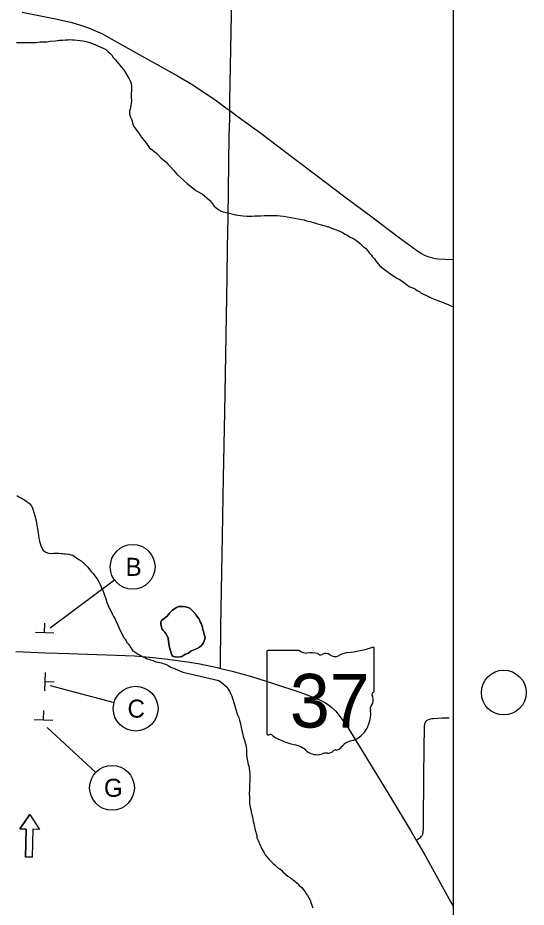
# Model space of a CAD drawing. Extents: x 1633.3 to 1707.6, y 1081.5 to 1106.
# Drawn here: x 1644.25 to 1648.64, y 1094.16 to 1101.85 of the extents above; entities that cross this region are included whole.
import ezdxf

# ---------------------------------------------------------------- set-up
doc = ezdxf.new("R2010")
doc.units = 0
for name, color, linetype in [('GM_X_Minor_Lake', 7, 'Continuous'), ('GM_X_Minor_River', 7, 'Continuous'), ('GM_X_State_Route', 7, 'Continuous'), ('GM_X_State_Shield', 7, 'Continuous'), ('GM_X_Township_Road', 7, 'Continuous'), ('SH_Data', 7, 'Continuous'), ('SH_Text', 7, 'Continuous'), ('SN_P_Signs', 7, 'Continuous')]:
    doc.layers.add(name, color=color, linetype=linetype)

msp = doc.modelspace()

# ---------------------------------------------------------------- linework, layer by layer
at = {"layer": 'GM_X_Minor_Lake'}
for points in [[(1645.4903, 1096.6358), (1645.5391, 1096.6727), (1645.5582, 1096.6965), (1645.5827, 1096.723), (1645.6044, 1096.7388), (1645.6206, 1096.7493), (1645.6395, 1096.7571), (1645.6583, 1096.7568), (1645.6771, 1096.7566), (1645.6986, 1096.7536), (1645.72, 1096.748), (1645.7387, 1096.7397), (1645.7599, 1096.7207), (1645.7732, 1096.7071), (1645.7837, 1096.6936), (1645.7943, 1096.6774), (1645.8128, 1096.653), (1645.8207, 1096.6395), (1645.8259, 1096.6261), (1645.8337, 1096.6099), (1645.8389, 1096.5964), (1645.8518, 1096.5507), (1645.8569, 1096.5292), (1645.862, 1096.5077), (1645.8671, 1096.4889), (1645.8642, 1096.4755), (1645.8587, 1096.4596), (1645.8531, 1096.4462), (1645.8449, 1096.4329), (1645.834, 1096.417), (1645.8204, 1096.4065), (1645.7988, 1096.3934), (1645.7691, 1096.3831), (1645.7448, 1096.37), (1645.7231, 1096.3542), (1645.6988, 1096.3438), (1645.6852, 1096.3359), (1645.6663, 1096.3255), (1645.6529, 1096.323), (1645.6259, 1096.318), (1645.6099, 1096.3208), (1645.5911, 1096.3238), (1645.5806, 1096.34), (1645.5754, 1096.3534), (1645.5702, 1096.3669), (1645.5624, 1096.3911), (1645.5599, 1096.4045), (1645.5574, 1096.418), (1645.5549, 1096.4367), (1645.5525, 1096.4582), (1645.5474, 1096.4824), (1645.5397, 1096.5039), (1645.5292, 1096.5228), (1645.5186, 1096.5363), (1645.5027, 1096.5526), (1645.4948, 1096.5661), (1645.4923, 1096.5795), (1645.4846, 1096.6064), (1645.4847, 1096.6198), (1645.4903, 1096.6358)], [(1645.834, 1096.417), (1645.8449, 1096.4329), (1645.8531, 1096.4462), (1645.8587, 1096.4596), (1645.8642, 1096.4755), (1645.8671, 1096.4889), (1645.862, 1096.5077), (1645.8569, 1096.5292), (1645.8518, 1096.5507), (1645.8389, 1096.5964), (1645.8337, 1096.6099), (1645.8259, 1096.6261), (1645.8207, 1096.6395), (1645.8128, 1096.653), (1645.7943, 1096.6774), (1645.7837, 1096.6936), (1645.7732, 1096.7071), (1645.7599, 1096.7207), (1645.7387, 1096.7397), (1645.72, 1096.748), (1645.6986, 1096.7536), (1645.6771, 1096.7566), (1645.6583, 1096.7568), (1645.6395, 1096.7571), (1645.6206, 1096.7493), (1645.6044, 1096.7388), (1645.5827, 1096.723), (1645.5582, 1096.6965), (1645.5391, 1096.6727), (1645.4903, 1096.6358)], [(1645.4903, 1096.6358), (1645.4847, 1096.6198), (1645.4846, 1096.6064), (1645.4923, 1096.5795), (1645.4948, 1096.5661), (1645.5027, 1096.5526), (1645.5186, 1096.5363), (1645.5292, 1096.5228), (1645.5397, 1096.5039), (1645.5474, 1096.4824), (1645.5525, 1096.4582), (1645.5549, 1096.4367), (1645.5574, 1096.418), (1645.5599, 1096.4045), (1645.5624, 1096.3911), (1645.5702, 1096.3669), (1645.5754, 1096.3534), (1645.5806, 1096.34), (1645.5911, 1096.3238), (1645.6099, 1096.3208), (1645.6259, 1096.318), (1645.6529, 1096.323), (1645.6663, 1096.3255), (1645.6852, 1096.3359), (1645.6988, 1096.3438), (1645.7231, 1096.3542), (1645.7448, 1096.37), (1645.7691, 1096.3831), (1645.7988, 1096.3934), (1645.8204, 1096.4065), (1645.834, 1096.417)]]:
    msp.add_lwpolyline(points, dxfattribs=at)
at = {"layer": 'GM_X_Minor_River'}
for points in [[(1644.2374, 1101.6373), (1644.2696, 1101.6368), (1644.2964, 1101.6365), (1644.326, 1101.6388), (1644.3556, 1101.6384), (1644.3824, 1101.638), (1644.4039, 1101.6378), (1644.4227, 1101.6402), (1644.4416, 1101.6426), (1644.4711, 1101.6422), (1644.5007, 1101.6445), (1644.5276, 1101.6495), (1644.5733, 1101.6516), (1644.6082, 1101.6565), (1644.6378, 1101.6588), (1644.662, 1101.6612), (1644.6835, 1101.6609), (1644.6996, 1101.6633), (1644.7157, 1101.6605), (1644.7345, 1101.6602), (1644.7613, 1101.6572), (1644.8149, 1101.6511), (1644.839, 1101.6454), (1644.8685, 1101.637), (1644.8925, 1101.6287), (1644.9086, 1101.6231), (1644.9273, 1101.6148), (1644.946, 1101.6065), (1644.9674, 1101.5982), (1644.986, 1101.5873), (1645.0101, 1101.5762), (1645.026, 1101.56), (1645.0446, 1101.5463), (1645.0605, 1101.5274), (1645.0737, 1101.5084), (1645.0922, 1101.4868), (1645.1054, 1101.4732), (1645.1187, 1101.4569), (1645.1292, 1101.4434), (1645.1425, 1101.4272), (1645.161, 1101.4055), (1645.1768, 1101.3812), (1645.1978, 1101.3461), (1645.211, 1101.3245), (1645.2188, 1101.3056), (1645.2267, 1101.2921), (1645.2292, 1101.276), (1645.2317, 1101.2599), (1645.2315, 1101.2439), (1645.2312, 1101.2224), (1645.2281, 1101.193), (1645.2277, 1101.1609), (1645.2301, 1101.1367), (1645.2298, 1101.1099), (1645.2268, 1101.0912), (1645.2211, 1101.0618), (1645.2155, 1101.0432), (1645.2152, 1101.0191), (1645.2229, 1100.9922), (1645.2307, 1100.9733), (1645.2359, 1100.9572), (1645.241, 1100.9384), (1645.2462, 1100.9222), (1645.2567, 1100.9033), (1645.2937, 1100.852), (1645.3095, 1100.8303), (1645.328, 1100.806), (1645.3518, 1100.7762), (1645.386, 1100.7249), (1645.4473, 1100.6812), (1645.4844, 1100.6405), (1645.5136, 1100.616), (1645.5322, 1100.6024), (1645.5481, 1100.5834), (1645.572, 1100.559), (1645.5958, 1100.5319), (1645.6222, 1100.4994), (1645.6514, 1100.4722), (1645.6806, 1100.4451), (1645.7125, 1100.4179), (1645.7524, 1100.3852), (1645.7869, 1100.358), (1645.8243, 1100.336), (1645.8456, 1100.3251), (1645.8616, 1100.3115), (1645.8828, 1100.2924), (1645.9067, 1100.2734), (1645.9252, 1100.249), (1645.9464, 1100.2219), (1645.9756, 1100.1975), (1646.0023, 1100.181), (1646.0236, 1100.1727), (1646.0504, 1100.167), (1646.0665, 1100.1641)], [(1646.0665, 1100.1641), (1646.0879, 1100.1585), (1646.1093, 1100.1528), (1646.1307, 1100.1472), (1646.1495, 1100.1443), (1646.1736, 1100.1413), (1646.1978, 1100.1383), (1646.23, 1100.1352), (1646.2568, 1100.1348), (1646.2756, 1100.1346), (1646.2971, 1100.137), (1646.324, 1100.1393), (1646.3508, 1100.1389), (1646.3777, 1100.1413), (1646.4126, 1100.1408), (1646.4476, 1100.1404), (1646.469, 1100.1401), (1646.4905, 1100.1398), (1646.5173, 1100.1368), (1646.5468, 1100.1337), (1646.5763, 1100.1306), (1646.7049, 1100.1048), (1646.7237, 1100.1019), (1646.7451, 1100.0936), (1646.7745, 1100.0879), (1646.804, 1100.0794), (1646.8307, 1100.071), (1646.8709, 1100.0598), (1646.9137, 1100.0485), (1646.9431, 1100.0401), (1646.9618, 1100.0318), (1646.9859, 1100.0235), (1647.0019, 1100.0179), (1647.0153, 1100.0124), (1647.0313, 1100.0041), (1647.0553, 1099.9931), (1647.0793, 1099.9794), (1647.1007, 1099.9684), (1647.122, 1099.9547), (1647.1513, 1099.9409), (1647.178, 1099.9245), (1647.2072, 1099.8973), (1647.2364, 1099.8702), (1647.2551, 1099.8592), (1647.2735, 1099.8349), (1647.2868, 1099.8186), (1647.3026, 1099.7997), (1647.3159, 1099.7834), (1647.3317, 1099.7645), (1647.3476, 1099.7428), (1647.3635, 1099.7239), (1647.3767, 1099.7076), (1647.3926, 1099.694), (1647.4192, 1099.6749), (1647.4512, 1099.6504), (1647.4911, 1099.6204), (1647.531, 1099.5958), (1647.5524, 1099.5875), (1647.5657, 1099.5766), (1647.579, 1099.5657), (1647.5976, 1099.552), (1647.6189, 1099.5357), (1647.6376, 1099.5247), (1647.6509, 1099.5165), (1647.6696, 1099.5109), (1647.6856, 1099.5027), (1647.7016, 1099.4917), (1647.7203, 1099.4835), (1647.7362, 1099.4699), (1647.7816, 1099.4478), (1647.8003, 1099.4395), (1647.8216, 1099.4286), (1647.8484, 1099.4175), (1647.8805, 1099.4064), (1647.9018, 1099.398), (1647.9259, 1099.387), (1647.9446, 1099.3787), (1647.9686, 1099.3704), (1647.9927, 1099.3593), (1648.0121, 1099.3526)], [(1644.2417, 1097.7183), (1644.2577, 1097.7074), (1644.2737, 1097.6991), (1644.2897, 1097.6882), (1644.3057, 1097.68), (1644.3217, 1097.669), (1644.3376, 1097.6581), (1644.3536, 1097.6472), (1644.3642, 1097.631), (1644.3747, 1097.6121), (1644.3824, 1097.5906), (1644.3901, 1097.561), (1644.3979, 1097.5341), (1644.4056, 1097.5072), (1644.4106, 1097.4804), (1644.413, 1097.4589), (1644.418, 1097.4321), (1644.4232, 1097.4105), (1644.4256, 1097.3918), (1644.4281, 1097.3757), (1644.4304, 1097.3462)], [(1644.4304, 1097.3462), (1644.4355, 1097.322), (1644.4433, 1097.3031), (1644.4484, 1097.2817), (1644.4667, 1097.2439), (1644.4853, 1097.2303), (1644.504, 1097.222), (1644.5201, 1097.2191), (1644.5362, 1097.2162), (1644.5577, 1097.2186), (1644.5738, 1097.2184), (1644.5899, 1097.2182), (1644.606, 1097.218), (1644.6221, 1097.2151), (1644.6355, 1097.2149), (1644.6516, 1097.2147), (1644.6651, 1097.2145), (1644.6892, 1097.2115), (1644.7079, 1097.2059), (1644.724, 1097.2004), (1644.7373, 1097.1921), (1644.7559, 1097.1785), (1644.7772, 1097.1648), (1644.7959, 1097.1539), (1644.8251, 1097.1267), (1644.8384, 1097.1131), (1644.8543, 1097.0969), (1644.8674, 1097.0779), (1644.8833, 1097.059), (1644.8992, 1097.0427), (1644.9124, 1097.0264), (1644.923, 1097.0102), (1644.9336, 1096.9967), (1644.9493, 1096.9697), (1644.9598, 1096.9481), (1644.9703, 1096.9266), (1644.9833, 1096.8969), (1644.9963, 1096.8646), (1645.0093, 1096.8243), (1645.0196, 1096.792), (1645.03, 1096.7651), (1645.0404, 1096.7408), (1645.0536, 1096.7192), (1645.064, 1096.695), (1645.0772, 1096.6707), (1645.0903, 1096.6491), (1645.1373, 1096.544), (1645.153, 1096.5117), (1645.1662, 1096.4874), (1645.1767, 1096.4739), (1645.1846, 1096.4604), (1645.1925, 1096.4469), (1645.2031, 1096.4333), (1645.2136, 1096.4198), (1645.2268, 1096.4009), (1645.2426, 1096.3739), (1645.264, 1096.3629), (1645.2879, 1096.3465), (1645.3012, 1096.3383), (1645.3146, 1096.3301), (1645.3333, 1096.3218), (1645.352, 1096.3135), (1645.368, 1096.3053), (1645.3814, 1096.3024), (1645.3947, 1096.2969), (1645.4161, 1096.2913), (1645.4428, 1096.2802), (1645.4616, 1096.2773), (1645.4776, 1096.2717), (1645.491, 1096.2688), (1645.5044, 1096.2633), (1645.5258, 1096.2577), (1645.5498, 1096.2466), (1645.5632, 1096.2384), (1645.5765, 1096.2302), (1645.5899, 1096.2274), (1645.6742, 1096.1881)], [(1645.6742, 1096.1881), (1645.9877, 1096.1175), (1646.0091, 1096.1014), (1646.0251, 1096.088), (1646.0545, 1096.0638), (1646.0678, 1096.0424), (1646.0785, 1096.0236), (1646.0891, 1095.9995), (1646.0998, 1095.9807), (1646.1051, 1095.962), (1646.1104, 1095.9459), (1646.1157, 1095.9272), (1646.121, 1095.9058), (1646.1263, 1095.887), (1646.1343, 1095.8656), (1646.1396, 1095.8469), (1646.1476, 1095.8201), (1646.1582, 1095.7959), (1646.1662, 1095.7745), (1646.1715, 1095.7531), (1646.1768, 1095.7263), (1646.1821, 1095.6969), (1646.1873, 1095.6701), (1646.1927, 1095.6514), (1646.198, 1095.6326), (1646.2033, 1095.6165), (1646.2086, 1095.5978), (1646.2139, 1095.5791), (1646.2192, 1095.5603), (1646.2218, 1095.5416), (1646.2245, 1095.5228), (1646.2244, 1095.5041), (1646.227, 1095.4827), (1646.227, 1095.4693), (1646.2297, 1095.4533), (1646.2323, 1095.4345), (1646.2349, 1095.4211), (1646.2376, 1095.4051), (1646.2402, 1095.3917), (1646.2455, 1095.3756), (1646.2482, 1095.3569), (1646.2508, 1095.3328), (1646.2534, 1095.3167), (1646.2533, 1095.2712), (1646.2533, 1095.2579), (1646.2533, 1095.2418), (1646.2505, 1095.2177), (1646.2505, 1095.199), (1646.2504, 1095.1749), (1646.2504, 1095.1616), (1646.2477, 1095.1482), (1646.2476, 1095.1321), (1646.2503, 1095.1161), (1646.2502, 1095.0947), (1646.2529, 1095.0759), (1646.2528, 1095.0572), (1646.2555, 1095.0385), (1646.2581, 1095.0197), (1646.2634, 1095.001), (1646.266, 1094.9796), (1646.2713, 1094.9555), (1646.2766, 1094.9367), (1646.2793, 1094.918), (1646.2846, 1094.8993), (1646.2899, 1094.8805), (1646.2925, 1094.8618), (1646.2978, 1094.8403), (1646.3004, 1094.8216), (1646.3058, 1094.8055), (1646.3084, 1094.7922), (1646.3137, 1094.7761), (1646.3164, 1094.7547), (1646.327, 1094.7332), (1646.3323, 1094.7198), (1646.3376, 1094.7065), (1646.343, 1094.6931), (1646.351, 1094.6797), (1646.3563, 1094.6636), (1646.3696, 1094.6395), (1646.3776, 1094.6261), (1646.3883, 1094.61), (1646.4016, 1094.5912), (1646.423, 1094.567), (1646.439, 1094.5509), (1646.455, 1094.5348), (1646.471, 1094.5214), (1646.4844, 1094.508), (1646.5004, 1094.4946), (1646.5137, 1094.4865), (1646.5271, 1094.4757), (1646.5405, 1094.4623), (1646.5858, 1094.4221), (1646.6072, 1094.4086), (1646.6206, 1094.3979), (1646.6393, 1094.3844), (1646.6633, 1094.3629), (1646.6847, 1094.3415), (1646.7034, 1094.3254), (1646.7194, 1094.3066), (1646.7327, 1094.2878), (1646.7434, 1094.269)], [(1646.7434, 1094.269), (1646.754, 1094.2556), (1646.7647, 1094.2369), (1646.7754, 1094.2154), (1646.7807, 1094.1967), (1646.7887, 1094.1806), (1646.794, 1094.1645), (1646.7993, 1094.1511)]]:
    msp.add_lwpolyline(points, dxfattribs=at)
at = {"layer": 'GM_X_State_Route'}
for points in [[(1644.2311, 1096.3693), (1644.4915, 1096.3571), (1644.6885, 1096.351), (1645.2573, 1096.3293), (1645.3886, 1096.32), (1645.5193, 1096.3056), (1645.7147, 1096.2786), (1645.8229, 1096.2604), (1645.973, 1096.2287), (1646.0005, 1096.2219)], [(1646.0005, 1096.2219), (1646.1008, 1096.1973), (1646.2697, 1096.1506), (1646.4581, 1096.0922), (1646.6868, 1096.0158), (1646.7695, 1095.9859), (1646.8244, 1095.9649), (1646.869, 1095.9449), (1646.9081, 1095.9249), (1646.9382, 1095.9048), (1646.9638, 1095.8836), (1646.9973, 1095.8513), (1647.0252, 1095.8179), (1647.0531, 1095.78), (1647.1018, 1095.7093), (1647.1717, 1095.5977), (1647.4779, 1095.0921), (1647.6481, 1094.8112), (1647.6935, 1094.7346), (1647.7696, 1094.603), (1647.9916, 1094.2004), (1648.0121, 1094.1633)]]:
    msp.add_lwpolyline(points, dxfattribs=at)
at = {"layer": 'GM_X_State_Shield'}
for p, q in [((1646.4005, 1096.365), (1646.4005, 1095.6605)), ((1646.6814, 1096.3771), (1646.4096, 1096.3771)), ((1647.3286, 1096.026), (1647.3286, 1096.3945)), ((1647.3285, 1096.0261), (1647.3286, 1096.026))]:
    msp.add_line(p, q, dxfattribs=at)
for centre, radius, start, end in [((1646.4111, 1096.3665), 0.0108, 98.1301, 188.1301), ((1646.7462, 1096.4589), 0.1043, 231.61951, 271.11188), ((1646.998, 1097.3374), 0.9842, 275.84447, 288.90645), ((1647.3183, 1096.3961), 0.0103, 351.86209, 97.738), ((1646.7807, 1095.9816), 0.3744, 80.48669, 94.98827), ((1646.8657, 1096.3701), 0.0301, 219.79206, 297.10237), ((1646.9099, 1096.2887), 0.0626, 54.46668, 119.14113), ((1646.9906, 1096.4004), 0.0753, 233.85621, 294.82819), ((1647.1235, 1096.1619), 0.198, 97.34618, 120.76885), ((1647.3262, 1095.999), 0.016, 107.94398, 210.33697), ((1647.2245, 1095.9524), 0.096, 340.03296, 23.64957), ((1647.3176, 1096.0246), 0.0111, 289.60381, 7.73413), ((1647.3656, 1095.8718), 0.0698, 136.8065, 186.92959), ((1647.0531, 1095.825), 0.2462, 292.30889, 8.98584), ((1646.4112, 1095.659), 0.0108, 171.95839, 258.30661), ((1646.4129, 1095.7311), 0.0828, 267.33899, 280.60386), ((1646.4298, 1095.6199), 0.0298, 29.74838, 93.27175), ((1646.8067, 1096.2528), 0.7108, 240.41292, 257.1985), ((1647.1569, 1095.4628), 0.1348, 94.40312, 142.57675), ((1646.5948, 1095.3441), 0.2224, 47.18416, 75.83597), ((1646.9951, 1095.4954), 0.0212, 65.75173, 132.64842), ((1646.9861, 1095.5923), 0.0795, 282.87319, 323.27711), ((1646.8353, 1095.6164), 0.1411, 230.70037, 286.29184), ((1646.9168, 1095.3728), 0.116, 85.69512, 111.20995), ((1646.9271, 1095.5636), 0.0752, 268.77702, 315.54927)]:
    msp.add_arc(centre, radius, start, end, dxfattribs=at)
at = {"layer": 'GM_X_Township_Road'}
for points in [[(1646.0805, 1101.0494), (1646.0808, 1101.1325), (1646.0963, 1101.8766), (1646.1004, 1102.3145), (1646.1092, 1102.7521), (1646.1124, 1103.0149), (1646.1259, 1103.759), (1646.1332, 1104.0873), (1646.1415, 1104.547), (1646.1539, 1105.1378), (1646.1639, 1105.7069), (1646.1696, 1106.0207)], [(1644.2875, 1101.9015), (1644.5875, 1101.8401), (1644.7149, 1101.8096), (1644.7988, 1101.7858), (1644.8606, 1101.765), (1644.9207, 1101.7399), (1644.9795, 1101.7115), (1645.0564, 1101.67), (1645.3225, 1101.5185), (1645.6285, 1101.3483), (1645.7603, 1101.2707), (1645.8524, 1101.2122), (1645.9424, 1101.1503), (1646.0484, 1101.0733), (1646.0805, 1101.0494)], [(1646.0005, 1096.2219), (1646.0009, 1096.2586), (1646.0048, 1096.5799), (1646.0181, 1097.3679), (1646.0267, 1097.8714), (1646.0381, 1098.4404), (1646.0595, 1099.6004), (1646.0622, 1099.8632), (1646.0673, 1100.1257), (1646.0771, 1100.8262), (1646.0812, 1100.9794), (1646.0805, 1101.0494)], [(1646.0805, 1101.0494), (1646.1541, 1100.9952), (1646.3482, 1100.8531), (1646.6271, 1100.6416), (1646.8372, 1100.484), (1647.0628, 1100.3109), (1647.309, 1100.1285), (1647.5362, 1099.9574), (1647.6949, 1099.8402), (1647.7321, 1099.8163), (1647.7714, 1099.7956), (1647.792, 1099.787), (1647.813, 1099.7796), (1647.8345, 1099.7738), (1647.8563, 1099.7694), (1647.8783, 1099.7663), (1647.9443, 1099.7618), (1648.0121, 1099.7604)], [(1647.6935, 1094.7346), (1647.7133, 1094.7469), (1647.7247, 1094.7548), (1647.7301, 1094.7595), (1647.7366, 1094.7661), (1647.7395, 1094.7696), (1647.7441, 1094.7761), (1647.7469, 1094.7807), (1647.7495, 1094.7872), (1647.7514, 1094.793), (1647.7529, 1094.8009), (1647.7543, 1094.8116), (1647.755, 1094.8244), (1647.755, 1094.8396), (1647.7564, 1094.889), (1647.7564, 1094.914), (1647.7569, 1095.0074), (1647.7586, 1095.1641), (1647.7588, 1095.2866), (1647.761, 1095.5316), (1647.7636, 1095.7066), (1647.7642, 1095.7194), (1647.7645, 1095.7241), (1647.7653, 1095.7322), (1647.7664, 1095.7378), (1647.7686, 1095.7462), (1647.7704, 1095.7515), (1647.7732, 1095.7571), (1647.7782, 1095.7643), (1647.7838, 1095.7699), (1647.7885, 1095.7739), (1647.7941, 1095.7777), (1647.8006, 1095.7811), (1647.8087, 1095.7839), (1647.8171, 1095.7862), (1647.8271, 1095.7882), (1647.8387, 1095.7894), (1647.9176, 1095.7932), (1647.9789, 1095.7953)]]:
    msp.add_lwpolyline(points, dxfattribs=at)
at = {"layer": 'SH_Data'}
msp.add_lwpolyline([(1633.3121, 1106.0207), (1648.0121, 1106.0207), (1648.0121, 1086.4207), (1633.3121, 1086.4207)], close=True, dxfattribs=at)
at = {"layer": 'SH_Text'}
for p, q in [((1644.5271, 1096.5723), (1645.0847, 1096.987)), ((1644.5275, 1096.075), (1645.0807, 1095.9262)), ((1644.5011, 1095.7099), (1644.9224, 1095.3217)), ((1644.3529, 1094.9586), (1644.2655, 1094.8329)), ((1644.3529, 1094.9586), (1644.435, 1094.8293)), ((1644.2655, 1094.8329), (1644.32, 1094.8318)), ((1644.32, 1094.8318), (1644.3149, 1094.5898)), ((1644.378, 1094.8305), (1644.3729, 1094.5885)), ((1644.435, 1094.8293), (1644.378, 1094.8305)), ((1644.3729, 1094.5885), (1644.3149, 1094.5898))]:
    msp.add_line(p, q, dxfattribs=at)
msp.add_lwpolyline([(1644.3149, 1094.5898), (1644.32, 1094.8318), (1644.2655, 1094.8329), (1644.3529, 1094.9586), (1644.435, 1094.8293), (1644.378, 1094.8305), (1644.3729, 1094.5886)], close=True, dxfattribs=at)
for centre in [(1645.2413, 1097.1007), (1648.4499, 1096.0129), (1645.2671, 1095.8738), (1645.0632, 1095.1888)]:
    msp.add_circle(centre, 0.1936, dxfattribs=at)
at = {"layer": 'SN_P_Signs'}
for p, q in [((1644.4803, 1096.5321), (1644.4823, 1096.6121)), ((1644.4003, 1096.5342), (1644.5602, 1096.5301)), ((1644.4843, 1096.1872), (1644.4793, 1096.0273)), ((1644.4818, 1096.1073), (1644.5618, 1096.1048)), ((1644.4704, 1095.7765), (1644.4725, 1095.8565)), ((1644.3905, 1095.7786), (1644.5504, 1095.7744))]:
    msp.add_line(p, q, dxfattribs=at)

# ---------------------------------------------------------------- texts
at = {"layer": 'GM_X_State_Shield'}
msp.add_text('37', height=0.46406, dxfattribs=at).set_placement((1646.6007, 1095.7102))
at = {"layer": 'SH_Text'}
for s, p in [('B', (1645.1805, 1097.0227)), ('C', (1645.197, 1095.7958)), ('G', (1644.9932, 1095.1108))]:
    msp.add_text(s, height=0.156, dxfattribs=at).set_placement(p)

doc.saveas('drawing.dxf')
